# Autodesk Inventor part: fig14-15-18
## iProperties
Created: 2005-03
Part Number: fig14-15-18
Document SubType Name: Sheet Metal
Designer: CADCIM
Manufacturer: Standard
Standards Organization: Custom
Author: CADCIM
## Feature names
1. Plate2
2. Plate4
3. Bend2
4. Plate5
5. Bend3
6. FlatPatternExtrusion1
7. Corner2
